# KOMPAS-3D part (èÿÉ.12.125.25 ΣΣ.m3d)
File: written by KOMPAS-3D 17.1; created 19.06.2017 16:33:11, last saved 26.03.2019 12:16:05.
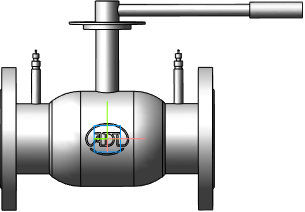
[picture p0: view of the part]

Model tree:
1. Операция без истории:2  (labels: Сталь 20  ГОСТ 1050-88)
